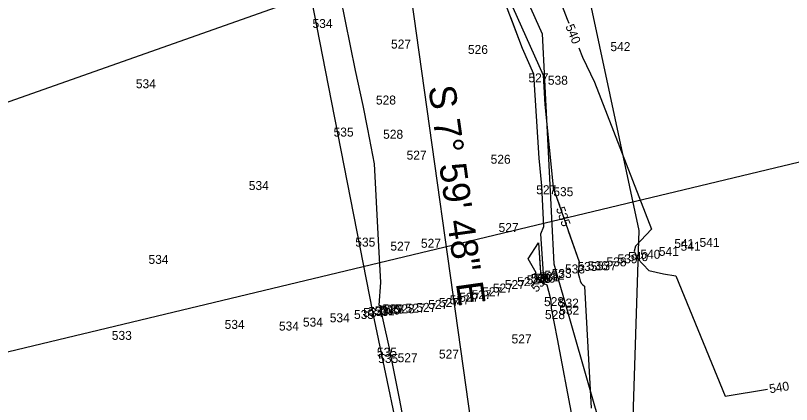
# Model space of a CAD drawing. Extents: x 1787461 to 1970323, y 938412 to 1118748.
# Drawn here: x 1967825.5 to 1967998.4, y 1118221.1 to 1118307.8 of the extents above; entities that cross this region are included whole.
import ezdxf

# ---------------------------------------------------------------- set-up
doc = ezdxf.new("R2010")
doc.units = 0
for name, color, linetype in [('Default', 7, 'Continuous'), ('HHA ADDITIONAL XSs', 7, 'Continuous'), ('Level 1', 7, 'Continuous'), ('RD_EX_DV_Prop', 7, 'Continuous'), ('RD_EX_Fence_Other', 7, 'Continuous'), ('RD_EX_H2O', 7, 'Continuous'), ('RD_HC_CL', 7, 'Continuous'), ('RD_HC_Data', 7, 'Continuous')]:
    doc.layers.add(name, color=color, linetype=linetype)

msp = doc.modelspace()

# ---------------------------------------------------------------- linework, layer by layer
at = {"layer": 'Default'}
for points in [[(1967864.89, 1118426.41), (1967863.9, 1118420.55), (1967876.68, 1118391.21), (1967879.95, 1118387.09), (1967900.78, 1118382.22), (1967903.7, 1118384.48), (1967908.55, 1118383.95), (1967906.91, 1118380.79), (1967912.33, 1118365.02), (1967916.69, 1118358.2), (1967920.57, 1118352.14), (1967924.83, 1118336.92), (1967926.82, 1118331.61), (1967934.7, 1118313.97), (1967936.36, 1118309.6), (1967943.07, 1118294.53), (1967943.46, 1118288.03), (1967945.34, 1118269.57), (1967945.36, 1118269.24), (1967945.39, 1118269.15), (1967945.43, 1118269.12), (1967946.15, 1118267.14), (1967946.71, 1118265.53)], [(1967864.89, 1118426.41), (1967863.9, 1118420.55), (1967876.68, 1118391.21), (1967879.95, 1118387.09), (1967900.78, 1118382.22), (1967903.7, 1118384.48), (1967908.55, 1118383.95), (1967906.91, 1118380.79), (1967912.33, 1118365.02), (1967916.69, 1118358.2), (1967920.57, 1118352.14), (1967924.83, 1118336.92), (1967926.82, 1118331.61), (1967934.7, 1118313.97), (1967936.36, 1118309.6), (1967943.07, 1118294.53), (1967943.46, 1118288.03), (1967945.34, 1118269.57), (1967945.36, 1118269.24), (1967945.39, 1118269.15), (1967945.43, 1118269.12), (1967946.15, 1118267.14), (1967946.71, 1118265.53)], [(1967864.89, 1118426.41), (1967863.9, 1118420.55), (1967876.68, 1118391.21), (1967879.95, 1118387.09), (1967900.78, 1118382.22), (1967903.7, 1118384.48), (1967908.55, 1118383.95), (1967906.91, 1118380.79), (1967912.33, 1118365.02), (1967916.69, 1118358.2), (1967920.57, 1118352.14), (1967924.83, 1118336.92), (1967926.82, 1118331.61), (1967934.7, 1118313.97), (1967936.36, 1118309.6), (1967943.07, 1118294.53), (1967943.46, 1118288.03), (1967945.34, 1118269.57), (1967945.36, 1118269.24), (1967945.39, 1118269.15), (1967945.43, 1118269.12), (1967946.15, 1118267.14), (1967946.71, 1118265.53)], [(1967864.89, 1118426.41), (1967863.9, 1118420.55), (1967876.68, 1118391.21), (1967879.95, 1118387.09), (1967900.78, 1118382.22), (1967903.7, 1118384.48), (1967908.55, 1118383.95), (1967906.91, 1118380.79), (1967912.33, 1118365.02), (1967916.69, 1118358.2), (1967920.57, 1118352.14), (1967924.83, 1118336.92), (1967926.82, 1118331.61), (1967934.7, 1118313.97), (1967936.36, 1118309.6), (1967943.07, 1118294.53), (1967943.46, 1118288.03), (1967945.34, 1118269.57), (1967945.36, 1118269.24), (1967945.39, 1118269.15), (1967945.43, 1118269.12), (1967946.15, 1118267.14), (1967946.71, 1118265.53)], [(1967864.89, 1118426.41), (1967863.9, 1118420.55), (1967876.68, 1118391.21), (1967879.95, 1118387.09), (1967900.78, 1118382.22), (1967903.7, 1118384.48), (1967908.55, 1118383.95), (1967906.91, 1118380.79), (1967912.33, 1118365.02), (1967916.69, 1118358.2), (1967920.57, 1118352.14), (1967924.83, 1118336.92), (1967926.82, 1118331.61), (1967934.7, 1118313.97), (1967936.36, 1118309.6), (1967943.07, 1118294.53), (1967943.46, 1118288.03), (1967945.34, 1118269.57), (1967945.36, 1118269.24), (1967945.39, 1118269.15), (1967945.43, 1118269.12), (1967946.15, 1118267.14), (1967946.71, 1118265.53)], [(1967864.89, 1118426.41), (1967863.9, 1118420.55), (1967876.68, 1118391.21), (1967879.95, 1118387.09), (1967900.78, 1118382.22), (1967903.7, 1118384.48), (1967908.55, 1118383.95), (1967906.91, 1118380.79), (1967912.33, 1118365.02), (1967916.69, 1118358.2), (1967920.57, 1118352.14), (1967924.83, 1118336.92), (1967926.82, 1118331.61), (1967934.7, 1118313.97), (1967936.36, 1118309.6), (1967943.07, 1118294.53), (1967943.46, 1118288.03), (1967945.34, 1118269.57), (1967945.36, 1118269.24), (1967945.39, 1118269.15), (1967945.43, 1118269.12), (1967946.15, 1118267.14), (1967946.71, 1118265.53)], [(1967932.03, 1118388.47), (1967945.98, 1118384.64), (1967930.44, 1118350.98), (1967935.02, 1118341.55), (1967938.33, 1118333.31), (1967948.45, 1118307.02), (1967948.8, 1118306.16)], [(1967932.03, 1118388.47), (1967945.98, 1118384.64), (1967930.44, 1118350.98), (1967935.02, 1118341.55), (1967938.33, 1118333.31), (1967948.45, 1118307.02), (1967948.8, 1118306.16)], [(1967932.03, 1118388.47), (1967945.98, 1118384.64), (1967930.44, 1118350.98), (1967935.02, 1118341.55), (1967938.33, 1118333.31), (1967948.45, 1118307.02), (1967948.8, 1118306.16)], [(1967932.03, 1118388.47), (1967945.98, 1118384.64), (1967930.44, 1118350.98), (1967935.02, 1118341.55), (1967938.33, 1118333.31), (1967948.45, 1118307.02), (1967948.8, 1118306.16)], [(1967932.03, 1118388.47), (1967945.98, 1118384.64), (1967930.44, 1118350.98), (1967935.02, 1118341.55), (1967938.33, 1118333.31), (1967948.45, 1118307.02), (1967948.8, 1118306.16)], [(1967932.03, 1118388.47), (1967945.98, 1118384.64), (1967930.44, 1118350.98), (1967935.02, 1118341.55), (1967938.33, 1118333.31), (1967948.45, 1118307.02), (1967948.8, 1118306.16)], [(1967932.03, 1118388.47), (1967945.98, 1118384.64), (1967930.44, 1118350.98), (1967935.02, 1118341.55), (1967938.33, 1118333.31), (1967948.45, 1118307.02), (1967948.8, 1118306.16)], [(1967859.06, 1118346.7), (1967865, 1118345.26), (1967872.8, 1118342.69), (1967878.29, 1118341.36), (1967881.24, 1118340.37), (1967883.71, 1118338.15), (1967892.81, 1118336.57), (1967896.13, 1118320.15), (1967897.87, 1118312.12), (1967901.22, 1118295.55), (1967902.9, 1118287.77), (1967903.97, 1118282.51), (1967905.46, 1118274.74), (1967906.33, 1118257.73), (1967906.82, 1118248.29), (1967906.47, 1118243.26), (1967906.86, 1118243.21), (1967906.88, 1118243.2), (1967907.2, 1118240.66), (1967908.91, 1118233.03), (1967909.01, 1118232.49), (1967910.98, 1118222.44), (1967913.74, 1118207.95)], [(1967859.06, 1118346.7), (1967865, 1118345.26), (1967872.8, 1118342.69), (1967878.29, 1118341.36), (1967881.24, 1118340.37), (1967883.71, 1118338.15), (1967892.81, 1118336.57), (1967896.13, 1118320.15), (1967897.87, 1118312.12), (1967901.22, 1118295.55), (1967902.9, 1118287.77), (1967903.97, 1118282.51), (1967905.46, 1118274.74), (1967906.33, 1118257.73), (1967906.82, 1118248.29), (1967906.47, 1118243.26), (1967906.86, 1118243.21), (1967906.88, 1118243.2), (1967907.2, 1118240.66), (1967908.91, 1118233.03), (1967909.01, 1118232.49), (1967910.98, 1118222.44), (1967913.74, 1118207.95)], [(1967859.06, 1118346.7), (1967865, 1118345.26), (1967872.8, 1118342.69), (1967878.29, 1118341.36), (1967881.24, 1118340.37), (1967883.71, 1118338.15), (1967892.81, 1118336.57), (1967896.13, 1118320.15), (1967897.87, 1118312.12), (1967901.22, 1118295.55), (1967902.9, 1118287.77), (1967903.97, 1118282.51), (1967905.46, 1118274.74), (1967906.33, 1118257.73), (1967906.82, 1118248.29), (1967906.47, 1118243.26), (1967906.86, 1118243.21), (1967906.88, 1118243.2), (1967907.2, 1118240.66), (1967908.91, 1118233.03), (1967909.01, 1118232.49), (1967910.98, 1118222.44), (1967913.74, 1118207.95)], [(1967859.06, 1118346.7), (1967865, 1118345.26), (1967872.8, 1118342.69), (1967878.29, 1118341.36), (1967881.24, 1118340.37), (1967883.71, 1118338.15), (1967892.81, 1118336.57), (1967896.13, 1118320.15), (1967897.87, 1118312.12), (1967901.22, 1118295.55), (1967902.9, 1118287.77), (1967903.97, 1118282.51), (1967905.46, 1118274.74), (1967906.33, 1118257.73), (1967906.82, 1118248.29), (1967906.47, 1118243.26), (1967906.86, 1118243.21), (1967906.88, 1118243.2), (1967907.2, 1118240.66), (1967908.91, 1118233.03), (1967909.01, 1118232.49), (1967910.98, 1118222.44), (1967913.74, 1118207.95)], [(1967859.06, 1118346.7), (1967865, 1118345.26), (1967872.8, 1118342.69), (1967878.29, 1118341.36), (1967881.24, 1118340.37), (1967883.71, 1118338.15), (1967892.81, 1118336.57), (1967896.13, 1118320.15), (1967897.87, 1118312.12), (1967901.22, 1118295.55), (1967902.9, 1118287.77), (1967903.97, 1118282.51), (1967905.46, 1118274.74), (1967906.33, 1118257.73), (1967906.82, 1118248.29), (1967906.47, 1118243.26), (1967906.86, 1118243.21), (1967906.88, 1118243.2), (1967907.2, 1118240.66), (1967908.91, 1118233.03), (1967909.01, 1118232.49), (1967910.98, 1118222.44), (1967913.74, 1118207.95)], [(1967859.06, 1118346.7), (1967865, 1118345.26), (1967872.8, 1118342.69), (1967878.29, 1118341.36), (1967881.24, 1118340.37), (1967883.71, 1118338.15), (1967892.81, 1118336.57), (1967896.13, 1118320.15), (1967897.87, 1118312.12), (1967901.22, 1118295.55), (1967902.9, 1118287.77), (1967903.97, 1118282.51), (1967905.46, 1118274.74), (1967906.33, 1118257.73), (1967906.82, 1118248.29), (1967906.47, 1118243.26), (1967906.86, 1118243.21), (1967906.88, 1118243.2), (1967907.2, 1118240.66), (1967908.91, 1118233.03), (1967909.01, 1118232.49), (1967910.98, 1118222.44), (1967913.74, 1118207.95)], [(1967949.61, 1118218.08), (1967946.31, 1118235.75), (1967944.94, 1118242.61), (1967944.85, 1118244.18), (1967944.76, 1118244.91), (1967944.02, 1118247.75), (1967943.34, 1118248.02), (1967942.59, 1118259.19), (1967943.24, 1118260.84), (1967942.82, 1118269.85), (1967942.19, 1118276.02), (1967941.05, 1118294.78), (1967938.5, 1118300.51), (1967933.41, 1118313.86)], [(1967897.87, 1118312.12), (1967901.22, 1118295.55), (1967902.9, 1118287.77), (1967903.97, 1118282.51), (1967905.46, 1118274.74), (1967906.33, 1118257.73), (1967906.82, 1118248.29), (1967906.47, 1118243.26), (1967906.86, 1118243.21), (1967906.88, 1118243.2), (1967907.2, 1118240.66), (1967908.91, 1118233.03), (1967909.01, 1118232.49), (1967910.98, 1118222.44), (1967913.74, 1118207.95)], [(1967936.36, 1118309.6), (1967943.07, 1118294.53), (1967943.46, 1118288.03), (1967945.34, 1118269.57), (1967945.36, 1118269.24), (1967945.39, 1118269.15), (1967945.43, 1118269.12), (1967946.15, 1118267.14), (1967951.13, 1118252.93), (1967950.92, 1118250.33), (1967951.2, 1118249.27), (1967951.36, 1118248.71), (1967951.56, 1118248.15), (1967951.95, 1118247.81), (1967952.3, 1118247.53), (1967953.8, 1118220.34)], [(1967949.61, 1118218.08), (1967946.31, 1118235.75), (1967944.94, 1118242.61), (1967944.85, 1118244.18), (1967944.76, 1118244.91), (1967944.02, 1118247.75), (1967943.34, 1118248.02), (1967942.59, 1118259.19), (1967943.24, 1118260.84), (1967942.82, 1118269.85), (1967942.19, 1118276.02), (1967941.05, 1118294.78), (1967938.5, 1118300.51), (1967935.89, 1118307.35)], [(1967949.61, 1118218.08), (1967946.31, 1118235.75), (1967944.94, 1118242.61), (1967944.85, 1118244.18), (1967944.76, 1118244.91), (1967944.02, 1118247.75), (1967943.34, 1118248.02), (1967942.59, 1118259.19), (1967943.24, 1118260.84), (1967942.82, 1118269.85), (1967942.19, 1118276.02), (1967941.05, 1118294.78), (1967938.5, 1118300.51), (1967935.89, 1118307.35)], [(1967949.61, 1118218.08), (1967946.31, 1118235.75), (1967944.94, 1118242.61), (1967944.85, 1118244.18), (1967944.76, 1118244.91), (1967944.02, 1118247.75), (1967943.34, 1118248.02), (1967942.59, 1118259.19), (1967943.24, 1118260.84), (1967942.82, 1118269.85), (1967942.19, 1118276.02), (1967941.05, 1118294.78), (1967938.5, 1118300.51), (1967935.89, 1118307.35)], [(1967949.61, 1118218.08), (1967946.31, 1118235.75), (1967944.94, 1118242.61), (1967944.85, 1118244.18), (1967944.76, 1118244.91), (1967944.02, 1118247.75), (1967943.34, 1118248.02), (1967942.59, 1118259.19), (1967943.24, 1118260.84), (1967942.82, 1118269.85), (1967942.19, 1118276.02), (1967941.05, 1118294.78), (1967938.5, 1118300.51), (1967935.89, 1118307.35)], [(1967949.61, 1118218.08), (1967946.31, 1118235.75), (1967944.94, 1118242.61), (1967944.85, 1118244.18), (1967944.76, 1118244.91), (1967944.02, 1118247.75), (1967943.34, 1118248.02), (1967942.59, 1118259.19), (1967943.24, 1118260.84), (1967942.82, 1118269.85), (1967942.19, 1118276.02), (1967941.05, 1118294.78), (1967938.5, 1118300.51), (1967935.89, 1118307.35)], [(1967949.61, 1118218.08), (1967946.31, 1118235.75), (1967944.94, 1118242.61), (1967944.85, 1118244.18), (1967944.76, 1118244.91), (1967944.02, 1118247.75), (1967943.34, 1118248.02), (1967942.59, 1118259.19), (1967943.24, 1118260.84), (1967942.82, 1118269.85), (1967942.19, 1118276.02), (1967941.05, 1118294.78), (1967938.5, 1118300.51), (1967935.89, 1118307.35)], [(1967951.04, 1118300.59), (1967951.87, 1118298.55), (1967954.57, 1118292.97), (1967967.23, 1118260.2), (1967963.66, 1118256.39), (1967963.37, 1118255.34), (1967964.14, 1118253.65), (1967966.67, 1118250.97), (1967969.93, 1118250.23), (1967972.63, 1118249.78), (1967983.64, 1118222.99), (1967993.08, 1118224.53)], [(1967951.04, 1118300.59), (1967951.87, 1118298.55), (1967954.57, 1118292.97), (1967967.23, 1118260.2), (1967963.66, 1118256.39), (1967963.37, 1118255.34), (1967964.14, 1118253.65), (1967966.67, 1118250.97), (1967969.93, 1118250.23), (1967972.63, 1118249.78), (1967983.64, 1118222.99), (1967993.08, 1118224.53)], [(1967951.04, 1118300.59), (1967951.87, 1118298.55), (1967954.57, 1118292.97), (1967967.23, 1118260.2), (1967963.66, 1118256.39), (1967963.37, 1118255.34), (1967964.14, 1118253.65), (1967966.67, 1118250.97), (1967969.93, 1118250.23), (1967972.63, 1118249.78), (1967983.64, 1118222.99), (1967993.08, 1118224.53)], [(1967951.04, 1118300.59), (1967951.87, 1118298.55), (1967954.57, 1118292.97), (1967967.23, 1118260.2), (1967963.66, 1118256.39), (1967963.37, 1118255.34), (1967964.14, 1118253.65), (1967966.67, 1118250.97), (1967969.93, 1118250.23), (1967972.63, 1118249.78), (1967983.64, 1118222.99), (1967993.08, 1118224.53)], [(1967951.04, 1118300.59), (1967951.87, 1118298.55), (1967954.57, 1118292.97), (1967967.23, 1118260.2), (1967963.66, 1118256.39), (1967963.37, 1118255.34), (1967964.14, 1118253.65), (1967966.67, 1118250.97), (1967969.93, 1118250.23), (1967972.63, 1118249.78), (1967983.64, 1118222.99), (1967993.08, 1118224.53)], [(1967951.04, 1118300.59), (1967951.87, 1118298.55), (1967954.57, 1118292.97), (1967967.23, 1118260.2), (1967963.66, 1118256.39), (1967963.37, 1118255.34), (1967964.14, 1118253.65), (1967966.67, 1118250.97), (1967969.93, 1118250.23), (1967972.63, 1118249.78), (1967983.64, 1118222.99), (1967993.08, 1118224.53)], [(1967951.04, 1118300.59), (1967951.87, 1118298.55), (1967954.57, 1118292.97), (1967967.23, 1118260.2), (1967963.66, 1118256.39), (1967963.37, 1118255.34), (1967964.14, 1118253.65), (1967966.67, 1118250.97), (1967969.93, 1118250.23), (1967972.63, 1118249.78), (1967983.64, 1118222.99), (1967993.08, 1118224.53)], [(1967948.69, 1118259.87), (1967951.13, 1118252.93), (1967950.92, 1118250.33), (1967951.2, 1118249.27), (1967951.36, 1118248.71), (1967951.56, 1118248.15), (1967951.95, 1118247.81), (1967952.3, 1118247.53), (1967953.8, 1118220.34)], [(1967948.69, 1118259.87), (1967951.13, 1118252.93), (1967950.92, 1118250.33), (1967951.2, 1118249.27), (1967951.36, 1118248.71), (1967951.56, 1118248.15), (1967951.95, 1118247.81), (1967952.3, 1118247.53), (1967953.8, 1118220.34)], [(1967948.69, 1118259.87), (1967951.13, 1118252.93), (1967950.92, 1118250.33), (1967951.2, 1118249.27), (1967951.36, 1118248.71), (1967951.56, 1118248.15), (1967951.95, 1118247.81), (1967952.3, 1118247.53), (1967953.8, 1118220.34)], [(1967948.69, 1118259.87), (1967951.13, 1118252.93), (1967950.92, 1118250.33), (1967951.2, 1118249.27), (1967951.36, 1118248.71), (1967951.56, 1118248.15), (1967951.95, 1118247.81), (1967952.3, 1118247.53), (1967953.8, 1118220.34)], [(1967948.69, 1118259.87), (1967951.13, 1118252.93), (1967950.92, 1118250.33), (1967951.2, 1118249.27), (1967951.36, 1118248.71), (1967951.56, 1118248.15), (1967951.95, 1118247.81), (1967952.3, 1118247.53), (1967953.8, 1118220.34)], [(1967948.69, 1118259.87), (1967951.13, 1118252.93), (1967950.92, 1118250.33), (1967951.2, 1118249.27), (1967951.36, 1118248.71), (1967951.56, 1118248.15), (1967951.95, 1118247.81), (1967952.3, 1118247.53), (1967953.8, 1118220.34)], [(1967939.77, 1118253.63), (1967942.03, 1118257.2), (1967942.68, 1118248.4), (1967941.65, 1118249.49), (1967940.98, 1118250.27), (1967941.2, 1118250.29), (1967941.52, 1118250.46), (1967939.77, 1118253.63)], [(1967939.77, 1118253.63), (1967942.03, 1118257.2), (1967942.45, 1118251.55)], [(1967939.77, 1118253.63), (1967942.03, 1118257.2), (1967942.45, 1118251.55)], [(1967939.77, 1118253.63), (1967942.03, 1118257.2), (1967942.45, 1118251.55)], [(1967939.77, 1118253.63), (1967942.03, 1118257.2), (1967942.45, 1118251.55)], [(1967939.77, 1118253.63), (1967942.03, 1118257.2), (1967942.45, 1118251.55)], [(1967939.77, 1118253.63), (1967942.03, 1118257.2), (1967942.45, 1118251.55)], [(1967941.28, 1118250.33), (1967941.52, 1118250.46), (1967939.77, 1118253.63)], [(1967941.28, 1118250.33), (1967941.52, 1118250.46), (1967939.77, 1118253.63)], [(1967941.28, 1118250.33), (1967941.52, 1118250.46), (1967939.77, 1118253.63)], [(1967941.28, 1118250.33), (1967941.52, 1118250.46), (1967939.77, 1118253.63)], [(1967941.28, 1118250.33), (1967941.52, 1118250.46), (1967939.77, 1118253.63)], [(1967941.28, 1118250.33), (1967941.52, 1118250.46), (1967939.77, 1118253.63)]]:
    msp.add_lwpolyline(points, dxfattribs=at)
at = {"layer": 'HHA ADDITIONAL XSs'}
msp.add_lwpolyline([(1969084.5, 1118456.85), (1968180.14, 1118318.35), (1967682.43, 1118198.9), (1966417.22, 1117847.18)], dxfattribs=at)
at = {"layer": 'Level 1'}
msp.add_line((1968062.38, 1118372.81), (1967713.43, 1118249.52), dxfattribs=at)
at = {"layer": 'RD_EX_DV_Prop'}
msp.add_line((1967910.14, 1118337.02), (1967929.83, 1118196.9), dxfattribs=at)
at = {"layer": 'RD_EX_Fence_Other'}
msp.add_lwpolyline([(1967919.7, 1118378.02), (1967936.64, 1118351.76), (1967953.58, 1118310.67), (1967964.44, 1118259.92), (1967962.38, 1118197.45), (1967934.48, 1118153.92), (1967925.2, 1118115.74), (1967925.02, 1118060.61), (1967940.38, 1118016.99), (1967944.7, 1118004.73)], dxfattribs=at)
at = {"layer": 'RD_EX_H2O'}
for points in [[(1967851.18, 1118399.4), (1967910.98, 1118393), (1967923.85, 1118346.18), (1967942.91, 1118303.76), (1967945.44, 1118252.51), (1967960.35, 1118200.64), (1967921.61, 1118157.98), (1967878.95, 1118126.47), (1967857.49, 1118083), (1967842.73, 1118040.05), (1967828.54, 1117994.01), (1967828.4, 1117944.09), (1967833.42, 1117912.71)], [(1967847.31, 1118356.81), (1967879.15, 1118347.14), (1967885.7, 1118340.94), (1967895.17, 1118292.21), (1967905.1, 1118241.75), (1967913.15, 1118203.17), (1967903.06, 1118190.95), (1967846.3, 1118148.6), (1967822.76, 1118102.41), (1967798.93, 1118056.05), (1967790.6, 1118001.77), (1967788.7, 1117944.97), (1967797.09, 1117898.55), (1967795.44, 1117890.32)]]:
    msp.add_lwpolyline(points, dxfattribs=at)
at = {"layer": 'RD_HC_CL'}
msp.add_line((1967910.14, 1118337.02), (1967929.83, 1118196.9), dxfattribs=at)

# ---------------------------------------------------------------- texts
at = {"layer": 'Default'}
for s, p in [('534', (1967891.7, 1118305.04)), ('527', (1967909.19, 1118300.47)), ('542', (1967958.08, 1118299.89)), ('526', (1967926.33, 1118299.26)), ('527', (1967939.81, 1118292.93)), ('534', (1967852.33, 1118291.62)), ('538', (1967944.14, 1118292.4)), ('528', (1967905.83, 1118287.99)), ('535', (1967896.4, 1118280.85)), ('528', (1967907.43, 1118280.36)), ('527', (1967912.66, 1118275.71)), ('526', (1967931.39, 1118274.79)), ('534', (1967877.5, 1118268.93)), ('527', (1967941.55, 1118268)), ('535', (1967945.36, 1118267.56)), ('527', (1967933.16, 1118259.57)), ('535', (1967901.23, 1118256.32)), ('527', (1967909.05, 1118255.42)), ('527', (1967915.86, 1118256.06)), ('541', (1967972.32, 1118256.02)), ('541', (1967973.72, 1118255.4)), ('541', (1967977.94, 1118256.27)), ('540', (1967962.04, 1118253.09)), ('540', (1967964.75, 1118253.61)), ('541', (1967968.87, 1118254.26)), ('534', (1967855.15, 1118252.47)), ('538', (1967957.21, 1118251.93)), ('539', (1967959.67, 1118252.6)), ('533', (1967947.96, 1118250.35)), ('535', (1967950.73, 1118250.9)), ('536', (1967953.04, 1118251.07)), ('537', (1967955.03, 1118251.04)), ('527', (1967939.41, 1118247.92)), ('529', (1967940.34, 1118248.22)), ('528', (1967940.4, 1118248.25)), ('530', (1967941.35, 1118248.29)), ('531', (1967942.28, 1118248.61)), ('532', (1967943.38, 1118248.93)), ('533', (1967944.99, 1118249.33)), ('527', (1967934.55, 1118246.86)), ('527', (1967937.29, 1118247.51)), ('527', (1967927.15, 1118244.61)), ('527', (1967929.5, 1118245.26)), ('527', (1967931.89, 1118246.08)), ('527', (1967919.85, 1118242.84)), ('527', (1967922.26, 1118243.48)), ('527', (1967924.4, 1118244.03)), ('528', (1967943.29, 1118243.06)), ('532', (1967946.59, 1118242.73)), ('531', (1967905.54, 1118241.03)), ('530', (1967906.79, 1118241.18)), ('529', (1967907.25, 1118241.44)), ('528', (1967907.65, 1118241.41)), ('528', (1967909.99, 1118241.46)), ('527', (1967912.42, 1118241.61)), ('527', (1967914.83, 1118241.77)), ('527', (1967917.48, 1118242.44)), ('532', (1967946.67, 1118241.15)), ('534', (1967895.54, 1118239.46)), ('535', (1967900.95, 1118240.19)), ('534', (1967902.99, 1118240.63)), ('533', (1967904.14, 1118240.88)), ('528', (1967943.5, 1118240.16)), ('534', (1967872.12, 1118237.98)), ('534', (1967884.22, 1118237.62)), ('534', (1967889.56, 1118238.49)), ('533', (1967846.97, 1118235.53)), ('527', (1967936.05, 1118234.74)), ('535', (1967906.05, 1118231.79)), ('527', (1967919.87, 1118231.38)), ('535', (1967906.33, 1118230.39)), ('527', (1967910.66, 1118230.56))]:
    msp.add_text(s, height=2, dxfattribs=at).set_placement(p)
for s, rotation, p in [('540', 291.9797, (1967948.02, 1118305.42)), ('540', 291.9797, (1967948.02, 1118305.42)), ('540', 291.9797, (1967948.02, 1118305.42)), ('540', 291.9797, (1967948.02, 1118305.42)), ('540', 291.9797, (1967948.02, 1118305.42)), ('540', 291.9797, (1967948.02, 1118305.42)), ('540', 291.9797, (1967948.02, 1118305.42)), ('535', 289.3117, (1967945.91, 1118264.8)), ('535', 289.3117, (1967945.91, 1118264.8)), ('535', 289.3117, (1967945.91, 1118264.8)), ('535', 289.3117, (1967945.91, 1118264.8)), ('535', 289.3117, (1967945.91, 1118264.8)), ('535', 289.3117, (1967945.91, 1118264.8)), ('530', 46.0804, (1967941.61, 1118246.01)), ('530', 46.0804, (1967941.61, 1118246.01)), ('530', 46.0804, (1967941.61, 1118246.01)), ('530', 46.0804, (1967941.61, 1118246.01)), ('530', 46.0804, (1967941.61, 1118246.01)), ('530', 46.0804, (1967941.61, 1118246.01)), ('540', 9.291, (1967993.63, 1118223.61)), ('540', 9.291, (1967993.63, 1118223.61)), ('540', 9.291, (1967993.63, 1118223.61)), ('540', 9.291, (1967993.63, 1118223.61)), ('540', 9.291, (1967993.63, 1118223.61)), ('540', 9.291, (1967993.63, 1118223.61)), ('540', 9.291, (1967993.63, 1118223.61))]:
    msp.add_text(s, height=2, rotation=rotation, dxfattribs=at).set_placement(p)
at = {"layer": 'RD_HC_Data'}
msp.add_text('S 7%%d 59\' 48" E', height=6, rotation=277.9968, dxfattribs=at).set_placement((1967917.49, 1118291.89))

doc.saveas('drawing.dxf')
